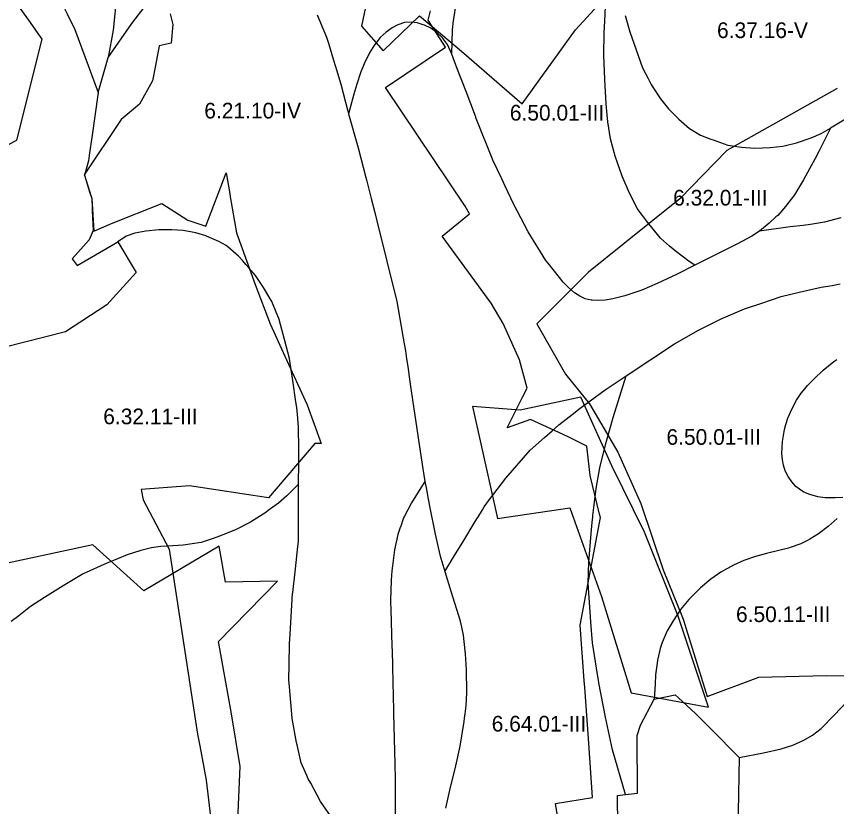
# Model space of a CAD drawing. Extents: x -555156 to -540209, y -1046851 to -1035695.
# Drawn here: x -542661 to -542138, y -1038700 to -1038196 of the extents above; entities that cross this region are included whole.
import ezdxf

# ---------------------------------------------------------------- set-up
doc = ezdxf.new("R2010")
doc.units = 0
for name, color, linetype in [('Vrstva 12', 7, 'Continuous'), ('Vrstva 27', 7, 'Continuous'), ('Vrstva 28', 7, 'Continuous'), ('Vrstva 29', 7, 'Continuous')]:
    doc.layers.add(name, color=color, linetype=linetype)

msp = doc.modelspace()

# ---------------------------------------------------------------- linework, layer by layer
at = {"layer": 'Vrstva 12'}
for points in [[(-542306.58, -1038766.88), (-542317.64, -1038698.07), (-542293.89, -1038694.45), (-542296.39, -1038659.78), (-542298.94, -1038624.16), (-542299.23, -1038619.77), (-542301.78, -1038584.38), (-542288.893989, -1038515.859034), (-542289.406731, -1038513.747022), (-542295.417027, -1038489.115812), (-542297.66, -1038470.26), (-542309.99, -1038464.23), (-542333.52, -1038453.33), (-542348.44, -1038458.61), (-542338.54, -1038439.08), (-542335.59, -1038433.24), (-542340.61, -1038415.19), (-542350.94, -1038392.12), (-542358.48, -1038379.16), (-542389.78, -1038336.3), (-542372.38, -1038322.26), (-542375.23, -1038317.2), (-542425.98, -1038241.7), (-542387.62, -1038215.78), (-542398.81, -1038198.57), (-542397.186761, -1038192.606435)], [(-542563.33, -1038194.53), (-542561.55, -1038201.37), (-542562.64, -1038213.36), (-542570.29, -1038214.97), (-542572.67, -1038227.47), (-542574.55, -1038237.33), (-542582.92, -1038252.2), (-542594.49, -1038262.03), (-542618.12, -1038297.22), (-542618.04, -1038297.53), (-542614.61, -1038308.66), (-542613.37, -1038312.46), (-542612.11, -1038333.11), (-542600.67, -1038328.24), (-542568.73, -1038315.66), (-542551.99, -1038326.19), (-542540.6, -1038330.07), (-542527.55, -1038296.02), (-542525.34, -1038309.43), (-542525.02, -1038311.29), (-542521.02, -1038334.17), (-542509.06, -1038367.27), (-542499.45, -1038392.37), (-542490.13, -1038413.02), (-542475.98, -1038443.85), (-542466.91, -1038468.6), (-542471.08, -1038468.69), (-542500.65, -1038503.29), (-542550.93, -1038495.58), (-542581.92, -1038498.02), (-542580.56, -1038504.59), (-542563.89, -1038535.91), (-542545.92, -1038654.02), (-542544.5, -1038661.46), (-542540.33, -1038683.26), (-542537.06, -1038711.98)]]:
    msp.add_lwpolyline(points, dxfattribs=at)
at = {"layer": 'Vrstva 28'}
for points in [[(-542383.58, -1038220.3), (-542383.3, -1038204.84), (-542382.54, -1038198.78), (-542382.25, -1038196.47), (-542381.06, -1038189.75), (-542378.82, -1038183.02), (-542377.56, -1038180.27), (-542375.68, -1038176.15), (-542374.52, -1038173.96), (-542371.95, -1038169.12), (-542367.32, -1038162.7), (-542361.79, -1038156.12), (-542354.92, -1038149.69), (-542342.52, -1038139.38), (-542328.18, -1038128.92), (-542320.58, -1038124), (-542308.64, -1038116.27), (-542288.85, -1038103.45), (-542273.03, -1038093.21), (-542264.35, -1038087.59)], [(-542605.36, -1038101.99), (-542601.33, -1038109.17), (-542598.49, -1038116.94), (-542597.97, -1038119.59), (-542597.2, -1038123.48), (-542596.4, -1038127.55), (-542595.65, -1038139.5), (-542596.82, -1038169.39), (-542597.04, -1038175.13), (-542597.3, -1038181.77), (-542599.65, -1038205.05), (-542602.79, -1038222.57)], [(-542814.84, -1038260.47), (-542791.36, -1038246.2), (-542739.18, -1038316.25), (-542709.61, -1038300.57), (-542687.09, -1038288.63), (-542661.06, -1038275.2), (-542644.88, -1038210.79), (-542653.5, -1038198.63), (-542667.1, -1038179.44), (-542648.82, -1038167.31), (-542628.21, -1038149.33), (-542634.67, -1038182.85), (-542629.06, -1038194.52), (-542624.17, -1038204.71), (-542609.2, -1038244.78)], [(-542602.79, -1038222.57), (-542587.68, -1038200.79), (-542577.68, -1038187.78)], [(-542228.72, -1038354.98), (-542232.23, -1038352.6), (-542241.17, -1038345.72), (-542242.43, -1038344.75), (-542244.81, -1038342.68), (-542250.53, -1038337.69), (-542258.11, -1038328.54), (-542265.43, -1038318.86), (-542268.74, -1038312.24), (-542270.4, -1038308.92), (-542275.1, -1038298.2), (-542279.54, -1038285.38), (-542282.42, -1038274.4), (-542284.25, -1038263.41), (-542284.66, -1038258.95), (-542285.07, -1038254.39), (-542285.3, -1038251.91), (-542286.18, -1038236.59), (-542286.7, -1038220.9), (-542286.44, -1038206.78), (-542286.1, -1038199.37), (-542285.65, -1038189.78)], [(-542085.84, -1038188.6), (-542085.99, -1038196.97), (-542087.04, -1038206.23), (-542088.98, -1038214.6), (-542093.01, -1038224.17), (-542097.34, -1038231.19), (-542103.02, -1038238.36), (-542107.95, -1038243.44), (-542114.37, -1038248.97), (-542121.24, -1038254.2), (-542129.46, -1038259.88), (-542142.15, -1038267.53)], [(-542469.53, -1038195.26), (-542463.56, -1038209.6), (-542462.43, -1038213.3), (-542459.08, -1038224.25), (-542457.03, -1038230.88), (-542454.6, -1038238.75), (-542454.43, -1038239.42), (-542450.09, -1038256.66), (-542449.67, -1038258.32)], [(-542273.14, -1038195.75), (-542270.15, -1038206.06), (-542262.02, -1038229), (-542258.52, -1038235.84), (-542256.52, -1038239.76), (-542256, -1038240.77), (-542250.59, -1038248.73), (-542245.51, -1038255.3), (-542238.94, -1038261.88), (-542232.07, -1038267.71), (-542225.05, -1038271.89), (-542218.45, -1038274.46), (-542216.98, -1038275.03), (-542207.57, -1038278.47), (-542198.91, -1038279.67)], [(-542383.58, -1038220.3), (-542386.51, -1038214.14), (-542389.65, -1038209.96), (-542392.93, -1038206.67), (-542396.96, -1038203.83), (-542401, -1038201.89), (-542402.03, -1038201.56), (-542405.18, -1038200.54), (-542405.72, -1038200.46), (-542409.36, -1038199.94), (-542413.84, -1038200.24), (-542418.18, -1038201.59), (-542421.76, -1038203.53), (-542425.64, -1038206.22), (-542429.38, -1038209.66), (-542432.78, -1038214.2), (-542432.96, -1038214.44), (-542436.12, -1038219.52), (-542436.4, -1038219.97), (-542439.68, -1038226.54), (-542440.06, -1038227.51), (-542441.69, -1038231.63), (-542441.92, -1038232.22), (-542444.31, -1038239.4), (-542446.26, -1038245.82), (-542449.04, -1038256.01), (-542449.67, -1038258.32)], [(-542609.2, -1038244.78), (-542602.79, -1038222.57)], [(-542294.13, -1038377.28), (-542294.76, -1038377.24), (-542298.68, -1038376.39), (-542302.1, -1038374.76), (-542305.51, -1038372.46), (-542309.18, -1038369.21), (-542312.66, -1038365.7), (-542322.3, -1038353.53), (-542323.64, -1038351.84), (-542334.88, -1038333.53), (-542344.29, -1038315.75), (-542349.67, -1038304.45), (-542351.84, -1038299.9), (-542357.36, -1038288.29), (-542368.05, -1038261.39), (-542368.64, -1038259.84), (-542374.62, -1038244.06), (-542380.44, -1038229.11), (-542383.58, -1038220.3)], [(-542609.2, -1038244.78), (-542613.32, -1038273.46), (-542614.73, -1038283.25), (-542615.45, -1038288.26), (-542618.04, -1038297.53), (-542614.02, -1038310.38), (-542613.37, -1038312.46)], [(-542449.67, -1038258.32), (-542443.4, -1038280.08), (-542438.56, -1038299.01), (-542437.98, -1038301.3), (-542435.13, -1038312.47), (-542432.88, -1038321.27), (-542431.52, -1038326.72)], [(-542198.91, -1038279.67), (-542190.39, -1038280.26), (-542180.54, -1038279.81), (-542172.47, -1038278.92), (-542163.81, -1038276.83), (-542154.55, -1038273.69), (-542148.12, -1038271), (-542142.15, -1038267.53)], [(-542142.15, -1038267.53), (-542149.41, -1038282.05), (-542151.86, -1038286.96), (-542158.11, -1038298.22), (-542159.33, -1038300.41), (-542165.16, -1038309.98), (-542170.83, -1038317.45), (-542175.76, -1038323.13), (-542176.92, -1038324.17), (-542181.29, -1038328.06), (-542187.41, -1038333.14)], [(-542613.37, -1038312.46), (-542613.11, -1038318.42), (-542613.03, -1038320.14), (-542612.44, -1038332.87), (-542615.04, -1038338.76), (-542625.77, -1038350.9), (-542622.63, -1038355.02), (-542596.67, -1038340.08)], [(-542431.52, -1038326.72), (-542418.7, -1038378.03), (-542414, -1038405.08), (-542413.21, -1038409.61), (-542412.49, -1038414.59), (-542411.78, -1038419.51), (-542410.16, -1038430.73), (-542407.26, -1038450.8), (-542406.21, -1038457.7), (-542404.86, -1038466.58), (-542402.09, -1038484.84), (-542400.86, -1038492.91)], [(-542135.47, -1038324.71), (-542145.93, -1038327.4), (-542154.89, -1038328.9), (-542159.54, -1038329.49), (-542167.88, -1038330.54), (-542187.41, -1038333.14)], [(-542481.51, -1038494.52), (-542481.35, -1038480.71), (-542481.25, -1038472.04), (-542481.51, -1038458.18), (-542482.21, -1038449.85), (-542482.55, -1038445.89), (-542483.32, -1038440.64), (-542484.9, -1038429.93), (-542485.55, -1038425.67), (-542486.17, -1038421.66), (-542487.26, -1038414.5), (-542490.39, -1038402.21), (-542493.89, -1038389.44), (-542494.05, -1038388.87), (-542495.68, -1038384.91), (-542498.53, -1038378.01), (-542499.12, -1038376.99), (-542503.76, -1038369.05), (-542508.99, -1038361.57), (-542512.91, -1038356.86), (-542514.96, -1038354.4), (-542517.05, -1038352.12), (-542519.74, -1038349.17), (-542526.62, -1038343.21), (-542527.51, -1038342.44), (-542532.29, -1038339.9), (-542538.34, -1038337.15), (-542540.5, -1038336.17), (-542546.93, -1038334.37), (-542554.99, -1038332.73), (-542562.31, -1038332.28), (-542565.42, -1038332.28), (-542570.53, -1038332.28), (-542578.89, -1038333.18), (-542585.76, -1038334.52), (-542591.29, -1038336.47), (-542596.67, -1038340.08)], [(-542187.41, -1038333.14), (-542192.34, -1038336.43), (-542201.56, -1038341.36), (-542224.94, -1038353.07), (-542228.72, -1038354.98)], [(-542596.67, -1038340.08), (-542585.03, -1038359.67), (-542603.63, -1038380.25), (-542630.03, -1038397.44), (-542669.31, -1038407.43), (-542683.88, -1038413.55), (-542687.72, -1038415.16)], [(-542228.72, -1038354.98), (-542239.96, -1038360.67), (-542252.68, -1038366.48), (-542262.41, -1038370.92), (-542273.33, -1038374.51), (-542281.01, -1038376.3), (-542284.58, -1038376.92), (-542285.88, -1038377.15)], [(-542272.56, -1038425.4), (-542241.71, -1038405), (-542226.29, -1038396.37), (-542211.91, -1038389.05), (-542208.93, -1038387.79), (-542197.01, -1038382.77), (-542185.99, -1038379.14), (-542173.59, -1038374.96), (-542162.24, -1038372.12), (-542148.2, -1038368.98), (-542141.09, -1038367.77), (-542135.95, -1038366.89)], [(-542285.88, -1038377.15), (-542290.32, -1038377.5), (-542294.13, -1038377.28)], [(-542134.38, -1038503.11), (-542139.26, -1038503.35), (-542145.65, -1038503.2), (-542150.28, -1038502.52), (-542155.4, -1038501.1), (-542159.06, -1038499.54), (-542161.84, -1038497.79), (-542164.19, -1038495.99), (-542166.84, -1038493), (-542169.06, -1038489.59), (-542171.02, -1038486.09), (-542172.13, -1038482.41), (-542172.81, -1038479), (-542173.16, -1038475.07), (-542173.07, -1038471.06), (-542172.73, -1038467.38), (-542172.13, -1038463.54), (-542171.45, -1038459.7), (-542170.6, -1038456.45), (-542169.4, -1038452.52), (-542166.82, -1038446.66), (-542163.91, -1038441.02), (-542160.84, -1038436.41), (-542158.59, -1038433.77), (-542156.83, -1038431.71), (-542152.22, -1038427.01), (-542147.27, -1038422.21), (-542146.84, -1038421.8), (-542140.07, -1038416.4), (-542138.12, -1038415.07)], [(-542388.11, -1038550.23), (-542381.94, -1038540.07), (-542376.1, -1038530.45), (-542369.39, -1038519.41), (-542367.78, -1038516.75), (-542367.15, -1038515.71), (-542364.21, -1038510.88), (-542363.03, -1038508.94), (-542360.21, -1038505.18), (-542349.31, -1038490.64), (-542333.76, -1038472.79), (-542324.58, -1038464.77), (-542319.68, -1038460.49), (-542315.43, -1038456.78), (-542306.99, -1038450.12), (-542301.83, -1038446.06), (-542285.89, -1038434.29), (-542272.56, -1038425.4)], [(-542272.87, -1038692.45), (-542281.2, -1038663.88), (-542285.65, -1038643.22), (-542289.83, -1038621.25), (-542290.11, -1038619.52), (-542290.71, -1038615.83), (-542294.01, -1038595.62), (-542295.04, -1038582.64), (-542295.32, -1038579.08), (-542296.63, -1038557.63), (-542296.37, -1038544.29), (-542294.8, -1038525.99), (-542294.16, -1038519), (-542293.82, -1038515.29), (-542293.75, -1038514.48), (-542292.93, -1038507.73), (-542291.66, -1038497.22), (-542289.31, -1038484.14), (-542285.39, -1038468.71), (-542280.68, -1038451.97), (-542272.56, -1038425.4)], [(-542481.51, -1038494.52), (-542488.97, -1038501.93), (-542494.2, -1038506.56), (-542497.77, -1038509.16), (-542500.8, -1038511.37), (-542502.41, -1038512.54), (-542505.65, -1038514.64), (-542512.12, -1038518.82), (-542521.68, -1038523.75), (-542531.84, -1038527.79), (-542535.84, -1038529.12), (-542543.49, -1038531.67), (-542554.99, -1038533.47), (-542564.77, -1038534.08), (-542569.18, -1038534.36), (-542575.27, -1038535.22), (-542581.99, -1038536.87), (-542590.65, -1038539.7), (-542602.99, -1038544.67), (-542603.65, -1038544.94), (-542618.88, -1038551.81), (-542631.58, -1038559.28), (-542643.53, -1038566.76), (-542652.49, -1038572.58), (-542659.81, -1038578.41)], [(-542487.46, -1038609.8), (-542487.16, -1038596.32), (-542486.78, -1038590.13), (-542485.21, -1038564.21), (-542485.17, -1038563.63), (-542483.67, -1038550.35), (-542483.46, -1038548.51), (-542481.87, -1038534.3), (-542481.51, -1038531.13), (-542481.51, -1038530.9), (-542481.51, -1038530.52), (-542481.51, -1038526.99), (-542481.51, -1038526.87), (-542481.51, -1038508.39), (-542481.51, -1038494.52)], [(-542400.86, -1038492.91), (-542401.22, -1038493.48), (-542409.48, -1038506.4), (-542411.84, -1038511.01), (-542413.84, -1038514.89), (-542414.45, -1038516.08), (-542416.51, -1038521.97), (-542416.6, -1038522.22), (-542418.11, -1038526.54), (-542420.2, -1038536.48), (-542421.59, -1038546.58), (-542422.03, -1038549.82), (-542422.27, -1038555.69), (-542422.81, -1038568.65), (-542422.58, -1038575.48), (-542422.39, -1038581.2), (-542422.06, -1038591.21), (-542421.7, -1038602.12), (-542421.54, -1038609.02), (-542421.22, -1038622.64), (-542421.1, -1038627.74), (-542420.8, -1038640.63), (-542420.04, -1038673.14), (-542419.99, -1038675.19), (-542419.87, -1038680.39), (-542419.8, -1038692.08), (-542419.62, -1038725.71)], [(-542400.86, -1038492.91), (-542400.07, -1038496.96), (-542398.67, -1038504.18), (-542398.56, -1038504.73), (-542398.26, -1038506.27), (-542397.82, -1038508.53), (-542394.24, -1038526.32), (-542391.25, -1038539.62), (-542388.11, -1038550.23)], [(-542137.81, -1038516.41), (-542143.64, -1038521.64), (-542149.76, -1038526.13), (-542155.29, -1038529.71), (-542156.72, -1038530.43), (-542160.97, -1038532.55), (-542167.9, -1038534.99), (-542169.03, -1038535.39), (-542175.12, -1038536.87), (-542182.88, -1038538.81), (-542189.9, -1038540.61), (-542197.52, -1038543.15), (-542203.94, -1038546.13), (-542212.01, -1038550.62), (-542218.58, -1038555.1), (-542225, -1038560.63), (-542232.47, -1038568.1), (-542237.85, -1038574.53), (-542242.48, -1038581.7), (-542246.28, -1038588.05), (-542246.51, -1038588.43), (-542247, -1038589.58), (-542249.5, -1038595.45), (-542250.71, -1038599.39), (-542251.29, -1038601.28), (-542252.4, -1038606.81), (-542252.79, -1038608.75), (-542253.68, -1038616.08), (-542254.01, -1038622.12), (-542254.52, -1038631.58)], [(-542388.11, -1038550.23), (-542384.23, -1038562.78), (-542378.4, -1038581.76), (-542378.31, -1038582.17), (-542378.17, -1038582.79), (-542376.42, -1038590.84), (-542375.97, -1038594.83), (-542375.07, -1038602.8), (-542374.47, -1038612.96), (-542374.32, -1038627.16), (-542374.34, -1038627.5), (-542374.77, -1038635.83), (-542375.38, -1038641.03), (-542375.71, -1038643.82), (-542375.97, -1038645.99), (-542378.51, -1038661.68), (-542381.34, -1038674.09), (-542385.09, -1038689.61), (-542387.78, -1038701.12)], [(-542659.81, -1038578.41), (-542664.81, -1038582.15)], [(-542456.64, -1038712.51), (-542467.36, -1038696.81), (-542473.64, -1038685.3), (-542475.2, -1038682.43), (-542476.2, -1038680.22), (-542479.84, -1038672.16), (-542482.42, -1038660.7), (-542482.72, -1038659.35), (-542485.59, -1038643.92), (-542485.61, -1038643.73), (-542487.31, -1038623.71), (-542487.68, -1038619.33), (-542487.46, -1038609.8)], [(-542272.87, -1038692.45), (-542265.22, -1038691.65), (-542265.55, -1038654.87), (-542263.27, -1038648.27), (-542254.52, -1038631.58)], [(-542254.52, -1038631.58), (-542241.18, -1038628.83), (-542239.29, -1038630.58), (-542228, -1038641.03), (-542218.21, -1038650.86), (-542200.33, -1038668.82)], [(-542200.33, -1038668.82), (-542184.9, -1038665.86), (-542173.55, -1038663.32), (-542166.23, -1038661.08), (-542159.06, -1038657.79), (-542153.68, -1038654.65), (-542148.01, -1038650.32), (-542139.79, -1038641.95), (-542131.45, -1038633.22), (-542126.79, -1038628.35)], [(-542200.33, -1038668.82), (-542201.33, -1038715.33), (-542189.48, -1038740.2), (-542186.59, -1038746.26), (-542186.12, -1038747.25), (-542186.61, -1038751.22), (-542187.27, -1038756.5), (-542187.81, -1038760.83), (-542184.6, -1038763.83), (-542195.59, -1038774.11), (-542193.74, -1038776.8)], [(-542284.83, -1038753.92), (-542277.18, -1038753.46), (-542277.51, -1038731.63), (-542278.1, -1038692.99), (-542272.87, -1038692.45)]]:
    msp.add_lwpolyline(points, dxfattribs=at)
at = {"layer": 'Vrstva 29'}
for points in [[(-542437.035992, -1038182.103007), (-542441.262005, -1038202.563008), (-542427.515997, -1038218.262993), (-542404.385004, -1038195.967007), (-542377.609007, -1038218.333998), (-542338.878008, -1038252.098007), (-542304.833994, -1038204.771001), (-542263.651006, -1038159.828994)], [(-542137.8, -1038242.330001), (-542167.115992, -1038258.520004), (-542208.274004, -1038281.733993), (-542238.319001, -1038312.664997), (-542273.706993, -1038341.169007), (-542296.609995, -1038359.400994), (-542329.449003, -1038392.299993), (-542311.251994, -1038424.381999), (-542295.847007, -1038443.348), (-542277.752003, -1038474.139003), (-542263.209005, -1038506.808004), (-542248.794996, -1038549.175995), (-542236.150995, -1038580.596005), (-542220.781005, -1038629.981001), (-542187.817005, -1038617.549997), (-542144.947999, -1038616.525994), (-542097.625008, -1038616.801008)], [(-542281.60791, -1038482.882996), (-542301.484009, -1038439.096008), (-542340.085999, -1038447.276001), (-542370.52301, -1038444.924011), (-542354.450989, -1038516.380005), (-542308.336975, -1038509.606995), (-542288.193909, -1038566.208984), (-542269.377991, -1038627.508972), (-542220.046021, -1038636.716003), (-542239.252014, -1038578.692017), (-542260.794983, -1038525.247009), (-542281.60791, -1038482.882996)], [(-542703.958008, -1038846.426025), (-542652.862, -1038845.10498), (-542594.921997, -1038844.344971), (-542599.822021, -1038805.922913), (-542594.127014, -1038774.455017), (-542593.682007, -1038774.481018), (-542528.036011, -1038774.856995), (-542520.179016, -1038708.812012), (-542518.653992, -1038674.47998), (-542524.507996, -1038639.778992), (-542532.473999, -1038594.856018), (-542494.877014, -1038556.390015), (-542527.976013, -1038557.044006), (-542532.151001, -1038534.049011), (-542580.085999, -1038562.590027), (-542612.674988, -1038533.138), (-542678.099976, -1038547.322998)]]:
    msp.add_lwpolyline(points, dxfattribs=at)

# ---------------------------------------------------------------- texts
at = {"layer": 'Vrstva 27'}
for s, p in [('6.37.16-V', (-542214.527974, -1038210.06)), ('6.21.10-IV', (-542541.56707, -1038261.35)), ('6.50.01-III', (-542346.676548, -1038262.69)), ('6.32.01-III', (-542242.516548, -1038316.88)), ('6.32.11-III', (-542606.006548, -1038456.34)), ('6.50.01-III', (-542246.766548, -1038469.44)), ('6.50.11-III', (-542202.426548, -1038582.48)), ('6.64.01-III', (-542358.236548, -1038652.28))]:
    msp.add_text(s, height=10, dxfattribs=at).set_placement(p)

doc.saveas('drawing.dxf')
